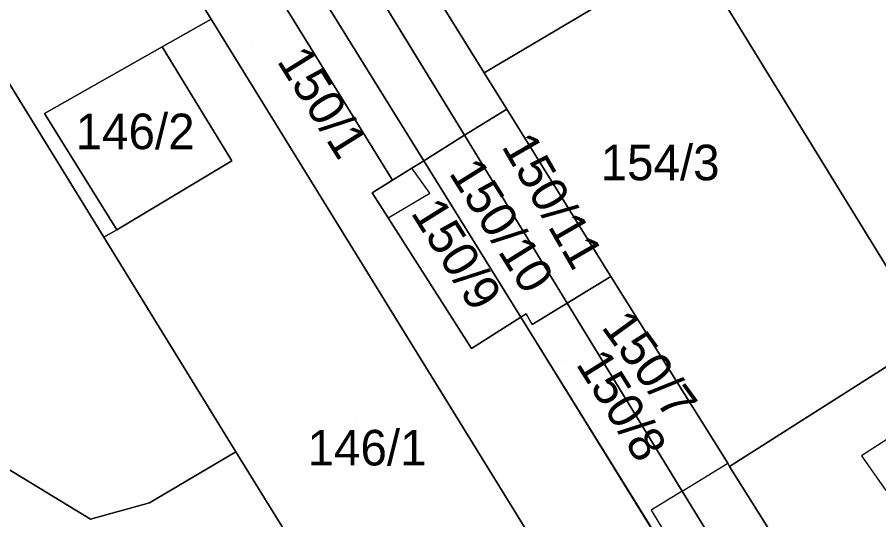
# Model space of a CAD drawing. Extents: x -263943 to -261149, y -1236934 to -1230686.
# Drawn here: x -262544.07 to -262495.61, y -1235802.01 to -1235773.72 of the extents above; entities that cross this region are included whole.
import ezdxf

# ---------------------------------------------------------------- set-up
doc = ezdxf.new("R2010")
doc.units = 0
for name, color, linetype in [('body_kn', 7, 'Continuous'), ('kladpar_druhypozemkov', 7, 'Continuous'), ('kladpar_hranice', 7, 'Continuous'), ('kladpar_parcelnecisla', 7, 'Continuous'), ('kladpar_plochy', 7, 'Continuous'), ('zappar_hrandruhpozemk', 7, 'Continuous')]:
    doc.layers.add(name, color=color, linetype=linetype)

msp = doc.modelspace()

# ---------------------------------------------------------------- linework, layer by layer
at = {"layer": 'body_kn'}
for p, q in [((-262533.17, -1235773.83), (-262533.17, -1235773.83)), ((-262535.91, -1235775.39), (-262535.91, -1235775.39)), ((-262517.8, -1235776.85), (-262517.8, -1235776.85)), ((-262517.8, -1235776.85), (-262517.8, -1235776.85)), ((-262516.53, -1235778.89), (-262516.53, -1235778.89)), ((-262516.53, -1235778.89), (-262516.53, -1235778.89)), ((-262542.53, -1235779.15), (-262542.53, -1235779.15)), ((-262542.53, -1235779.15), (-262542.53, -1235779.15)), ((-262518.91, -1235780.37), (-262518.91, -1235780.37)), ((-262518.91, -1235780.37), (-262518.91, -1235780.37)), ((-262532, -1235781.81), (-262532, -1235781.81)), ((-262521.2, -1235781.8), (-262521.2, -1235781.8)), ((-262521.2, -1235781.8), (-262521.2, -1235781.8)), ((-262521.87, -1235782.22), (-262521.87, -1235782.22)), ((-262521.87, -1235782.22), (-262521.87, -1235782.22)), ((-262522.96, -1235782.9), (-262522.96, -1235782.9)), ((-262522.96, -1235782.9), (-262522.96, -1235782.9)), ((-262524.1, -1235783.61), (-262524.1, -1235783.61)), ((-262520.87, -1235783.62), (-262520.87, -1235783.62)), ((-262523.21, -1235785.01), (-262523.21, -1235785.01)), ((-262523.21, -1235785.01), (-262523.21, -1235785.01)), ((-262538.47, -1235785.69), (-262538.47, -1235785.69)), ((-262539.2, -1235786.1), (-262539.2, -1235786.1)), ((-262510.68, -1235788.32), (-262510.68, -1235788.32)), ((-262510.68, -1235788.32), (-262510.68, -1235788.32)), ((-262513.14, -1235789.82), (-262513.14, -1235789.82)), ((-262515.75, -1235790.61), (-262515.75, -1235790.61)), ((-262515.45, -1235790.42), (-262515.45, -1235790.42)), ((-262515.11, -1235791.02), (-262515.11, -1235791.02)), ((-262518.51, -1235792.36), (-262518.51, -1235792.36)), ((-262531.78, -1235798.18), (-262531.78, -1235798.18)), ((-262531.78, -1235798.18), (-262531.78, -1235798.18)), ((-262496.58, -1235798.41), (-262496.58, -1235798.41)), ((-262504.11, -1235798.82), (-262504.11, -1235798.82)), ((-262504, -1235799), (-262504, -1235799)), ((-262506.67, -1235800.4), (-262506.67, -1235800.4)), ((-262506.67, -1235800.4), (-262506.67, -1235800.4)), ((-262536.63, -1235801.05), (-262536.63, -1235801.05)), ((-262508.42, -1235801.47), (-262508.42, -1235801.47)), ((-262539.95, -1235801.97), (-262539.95, -1235801.97))]:
    msp.add_line(p, q, dxfattribs=at)
at = {"layer": 'kladpar_druhypozemkov'}
for p, q in [((-262530.84, -1235775.34), (-262530.84, -1235775.34)), ((-262537.47, -1235778.5), (-262537.47, -1235778.5)), ((-262517.27, -1235780.12), (-262517.27, -1235780.12)), ((-262507.67, -1235780.9), (-262507.67, -1235780.9)), ((-262519.28, -1235781.91), (-262519.28, -1235781.91)), ((-262517.83, -1235788.26), (-262517.83, -1235788.26)), ((-262511.4, -1235790.94), (-262511.4, -1235790.94)), ((-262513.42, -1235793.1), (-262513.42, -1235793.1)), ((-262525.07, -1235796.5), (-262525.07, -1235796.5))]:
    msp.add_line(p, q, dxfattribs=at)
at = {"layer": 'kladpar_hranice'}
for p, q in [((-262521.2, -1235781.8), (-262543.94, -1235745.11)), ((-262543.94, -1235745.11), (-262521.2, -1235781.8)), ((-262518.91, -1235780.37), (-262537.03, -1235750.74)), ((-262537.03, -1235750.74), (-262518.91, -1235780.37)), ((-262518.91, -1235780.37), (-262516.53, -1235778.89)), ((-262518.91, -1235780.37), (-262521.2, -1235781.8)), ((-262521.2, -1235781.8), (-262518.91, -1235780.37)), ((-262518.91, -1235780.37), (-262513.14, -1235789.82)), ((-262513.14, -1235789.82), (-262518.91, -1235780.37)), ((-262521.87, -1235782.22), (-262521.2, -1235781.8)), ((-262521.2, -1235781.8), (-262515.75, -1235790.61)), ((-262515.75, -1235790.61), (-262521.2, -1235781.8)), ((-262513.14, -1235789.82), (-262510.68, -1235788.32)), ((-262515.75, -1235790.61), (-262504.71, -1235808.42)), ((-262504.71, -1235808.42), (-262515.75, -1235790.61))]:
    msp.add_line(p, q, dxfattribs=at)
for points in [[(-262541.39, -1235743.6), (-262539.16, -1235742.28), (-262528.72, -1235759.26), (-262517.8, -1235776.85)], [(-262522.96, -1235782.9), (-262545.68, -1235746.14), (-262543.94, -1235745.11)], [(-262509.8, -1235811.73), (-262533.17, -1235773.83), (-262535.2, -1235770.52), (-262548.92, -1235748.31), (-262549, -1235748.17), (-262545.68, -1235746.14), (-262522.96, -1235782.9), (-262524.1, -1235783.61), (-262523.21, -1235785.01), (-262518.51, -1235792.36), (-262515.75, -1235790.61)], [(-262542.53, -1235779.15), (-262538.47, -1235785.69), (-262539.2, -1235786.1), (-262544.99, -1235776.68), (-262548.44, -1235771.06), (-262550.62, -1235767.5), (-262557.92, -1235755.61), (-262559.32, -1235753.33), (-262549.6, -1235747.32), (-262549, -1235748.17), (-262548.92, -1235748.31), (-262535.2, -1235770.52), (-262533.17, -1235773.83), (-262535.91, -1235775.39), (-262542.53, -1235779.15)], [(-262528.72, -1235759.26), (-262520.33, -1235754.87), (-262519.51, -1235756.18), (-262516.32, -1235754.26), (-262517.03, -1235753.13), (-262516.64, -1235752.93), (-262514.54, -1235756.27), (-262509.27, -1235764.66), (-262506.14, -1235769.93), (-262517.8, -1235776.85), (-262528.72, -1235759.26)], [(-262531.78, -1235798.18), (-262536.63, -1235801.05), (-262539.95, -1235801.97), (-262549.37, -1235796.26), (-262555.31, -1235791.15), (-262561.99, -1235780.36), (-262572.32, -1235764.21), (-262573.59, -1235762.17), (-262570.55, -1235760.29), (-262569.21, -1235762.34), (-262571.73, -1235763.96), (-262570.81, -1235765.31), (-262567.49, -1235770.17), (-262565.09, -1235768.67), (-262564.94, -1235768.9), (-262554.5, -1235775.12), (-262548.44, -1235771.06), (-262544.99, -1235776.68), (-262539.2, -1235786.1), (-262531.78, -1235798.18)], [(-262576.07, -1235768.53), (-262575.73, -1235766.24), (-262572.32, -1235764.21), (-262561.99, -1235780.36), (-262555.31, -1235791.15), (-262549.37, -1235796.26), (-262539.95, -1235801.97), (-262536.63, -1235801.05), (-262531.78, -1235798.18), (-262515.86, -1235823.92), (-262489.14, -1235866.73)], [(-262467.61, -1235831.73), (-262477.05, -1235816.42), (-262492.69, -1235791.8), (-262504.11, -1235773.23), (-262490.4, -1235765.13), (-262475.84, -1235788.48), (-262462.67, -1235809.8), (-262437.59, -1235849.88), (-262453.44, -1235854.31), (-262467.61, -1235831.73)], [(-262510.68, -1235788.32), (-262516.53, -1235778.89), (-262517.8, -1235776.85), (-262506.14, -1235769.93), (-262504.11, -1235773.23), (-262492.69, -1235791.8), (-262504, -1235799), (-262504.11, -1235798.82), (-262510.68, -1235788.32)], [(-262531.78, -1235798.18), (-262539.2, -1235786.1), (-262538.47, -1235785.69), (-262532, -1235781.81), (-262535.91, -1235775.39), (-262533.17, -1235773.83), (-262509.8, -1235811.73), (-262506.58, -1235817.08), (-262515.86, -1235823.92), (-262531.78, -1235798.18)], [(-262542.53, -1235779.15), (-262535.91, -1235775.39), (-262532, -1235781.81), (-262538.47, -1235785.69), (-262542.53, -1235779.15)], [(-262517.8, -1235776.85), (-262516.53, -1235778.89), (-262518.91, -1235780.37)], [(-262516.53, -1235778.89), (-262510.68, -1235788.32), (-262513.14, -1235789.82)], [(-262521.2, -1235781.8), (-262521.87, -1235782.22), (-262522.96, -1235782.9)], [(-262515.75, -1235790.61), (-262518.51, -1235792.36), (-262523.21, -1235785.01), (-262524.1, -1235783.61), (-262522.96, -1235782.9), (-262521.87, -1235782.22)], [(-262510.68, -1235788.32), (-262504.11, -1235798.82), (-262504, -1235799), (-262500.01, -1235805.37), (-262501.89, -1235806.59), (-262502.6, -1235807.05)], [(-262515.75, -1235790.61), (-262515.45, -1235790.42), (-262515.11, -1235791.02), (-262513.14, -1235789.82)], [(-262513.14, -1235789.82), (-262515.11, -1235791.02), (-262515.45, -1235790.42), (-262515.75, -1235790.61)], [(-262502.6, -1235807.05), (-262504.24, -1235804.37), (-262506.67, -1235800.4), (-262513.14, -1235789.82)], [(-262513.14, -1235789.82), (-262506.67, -1235800.4), (-262504.24, -1235804.37), (-262502.6, -1235807.05)], [(-262458.14, -1235862.12), (-262467.75, -1235846.97), (-262471.24, -1235841.22), (-262475.72, -1235844.19), (-262500.01, -1235805.37), (-262504, -1235799), (-262492.69, -1235791.8), (-262477.05, -1235816.42), (-262467.61, -1235831.73), (-262453.44, -1235854.31), (-262450.19, -1235859.48)]]:
    msp.add_lwpolyline(points, dxfattribs=at)
at = {"layer": 'kladpar_plochy'}
for p, q in [((-262504, -1235799), (-262492.69, -1235791.8)), ((-262500.01, -1235805.37), (-262504, -1235799))]:
    msp.add_line(p, q, dxfattribs=at)
for points in [[(-262517.8, -1235776.85), (-262516.53, -1235778.89), (-262518.91, -1235780.37), (-262537.03, -1235750.74), (-262535.15, -1235749.65), (-262537.86, -1235744.98), (-262539.87, -1235746.09), (-262541.39, -1235743.6), (-262539.16, -1235742.28), (-262528.72, -1235759.26)], [(-262518.91, -1235780.37), (-262521.2, -1235781.8), (-262543.94, -1235745.11), (-262541.39, -1235743.6), (-262539.87, -1235746.09), (-262541.52, -1235747.01), (-262538.64, -1235751.68), (-262537.03, -1235750.74)], [(-262522.96, -1235782.9), (-262545.68, -1235746.14), (-262543.94, -1235745.11), (-262521.2, -1235781.8), (-262521.87, -1235782.22)], [(-262509.8, -1235811.73), (-262533.17, -1235773.83), (-262535.2, -1235770.52), (-262548.92, -1235748.31), (-262549, -1235748.17), (-262545.68, -1235746.14), (-262522.96, -1235782.9), (-262524.1, -1235783.61), (-262523.21, -1235785.01), (-262518.51, -1235792.36), (-262515.75, -1235790.61), (-262504.71, -1235808.42)], [(-262542.53, -1235779.15), (-262538.47, -1235785.69), (-262539.2, -1235786.1), (-262544.99, -1235776.68), (-262548.44, -1235771.06), (-262550.62, -1235767.5), (-262557.92, -1235755.61), (-262559.32, -1235753.33), (-262549.6, -1235747.32), (-262549, -1235748.17), (-262548.92, -1235748.31), (-262535.2, -1235770.52), (-262533.17, -1235773.83), (-262535.91, -1235775.39)], [(-262528.72, -1235759.26), (-262520.33, -1235754.87), (-262519.51, -1235756.18), (-262516.32, -1235754.26), (-262517.03, -1235753.13), (-262516.64, -1235752.93), (-262514.54, -1235756.27), (-262509.27, -1235764.66), (-262506.14, -1235769.93), (-262517.8, -1235776.85)], [(-262531.78, -1235798.18), (-262536.63, -1235801.05), (-262539.95, -1235801.97), (-262549.37, -1235796.26), (-262555.31, -1235791.15), (-262561.99, -1235780.36), (-262572.32, -1235764.21), (-262573.59, -1235762.17), (-262570.55, -1235760.29), (-262569.21, -1235762.34), (-262571.73, -1235763.96), (-262570.81, -1235765.31), (-262567.49, -1235770.17), (-262565.09, -1235768.67), (-262564.94, -1235768.9), (-262554.5, -1235775.12), (-262548.44, -1235771.06), (-262544.99, -1235776.68), (-262539.2, -1235786.1)], [(-262467.61, -1235831.73), (-262477.05, -1235816.42), (-262492.69, -1235791.8), (-262504.11, -1235773.23), (-262490.4, -1235765.13), (-262475.84, -1235788.48), (-262462.67, -1235809.8), (-262437.59, -1235849.88), (-262453.44, -1235854.31)], [(-262510.68, -1235788.32), (-262516.53, -1235778.89), (-262517.8, -1235776.85), (-262506.14, -1235769.93), (-262504.11, -1235773.23), (-262492.69, -1235791.8), (-262504, -1235799), (-262504.11, -1235798.82)], [(-262531.78, -1235798.18), (-262539.2, -1235786.1), (-262538.47, -1235785.69), (-262532, -1235781.81), (-262535.91, -1235775.39), (-262533.17, -1235773.83), (-262509.8, -1235811.73), (-262506.58, -1235817.08), (-262515.86, -1235823.92)], [(-262542.53, -1235779.15), (-262535.91, -1235775.39), (-262532, -1235781.81), (-262538.47, -1235785.69)], [(-262516.53, -1235778.89), (-262510.68, -1235788.32), (-262513.14, -1235789.82), (-262518.91, -1235780.37)], [(-262521.2, -1235781.8), (-262518.91, -1235780.37), (-262513.14, -1235789.82), (-262515.11, -1235791.02), (-262515.45, -1235790.42), (-262515.75, -1235790.61)], [(-262521.87, -1235782.22), (-262521.2, -1235781.8), (-262515.75, -1235790.61), (-262518.51, -1235792.36), (-262523.21, -1235785.01), (-262524.1, -1235783.61), (-262522.96, -1235782.9)], [(-262510.68, -1235788.32), (-262504.11, -1235798.82), (-262504, -1235799), (-262500.01, -1235805.37), (-262501.89, -1235806.59), (-262502.6, -1235807.05), (-262504.24, -1235804.37), (-262506.67, -1235800.4), (-262513.14, -1235789.82)], [(-262502.6, -1235807.05), (-262504.71, -1235808.42), (-262515.75, -1235790.61), (-262515.45, -1235790.42), (-262515.11, -1235791.02), (-262513.14, -1235789.82), (-262506.67, -1235800.4), (-262504.24, -1235804.37)]]:
    msp.add_lwpolyline(points, close=True, dxfattribs=at)
msp.add_lwpolyline([(-262605.67, -1235871.49), (-262620.33, -1235848.64), (-262635.19, -1235825.26), (-262636.43, -1235823.31), (-262646.33, -1235807.76), (-262611.04, -1235787.25), (-262583.9, -1235771.05), (-262582.11, -1235772.41), (-262576.07, -1235768.53), (-262575.73, -1235766.24), (-262572.32, -1235764.21), (-262561.99, -1235780.36), (-262555.31, -1235791.15), (-262549.37, -1235796.26), (-262539.95, -1235801.97), (-262536.63, -1235801.05), (-262531.78, -1235798.18), (-262515.86, -1235823.92), (-262489.14, -1235866.73)], dxfattribs=at)
at = {"layer": 'zappar_hrandruhpozemk'}
for p, q in [((-262520.87, -1235783.62), (-262521.87, -1235782.22)), ((-262523.21, -1235785.01), (-262520.87, -1235783.62)), ((-262506.67, -1235800.4), (-262504.11, -1235798.82)), ((-262506.67, -1235800.4), (-262508.42, -1235801.47)), ((-262508.42, -1235801.47), (-262505.11, -1235806.82))]:
    msp.add_line(p, q, dxfattribs=at)
msp.add_lwpolyline([(-262491.08, -1235794.85), (-262496.58, -1235798.41), (-262495.22, -1235800.36)], dxfattribs=at)

# ---------------------------------------------------------------- texts
at = {"layer": 'kladpar_parcelnecisla'}
for s, rotation, p in [('150/1', 302, (-262529.5, -1235776.186)), ('150/11', 300, (-262516.86, -1235780.989)), ('150/10', 302, (-262519.827, -1235782.491)), ('150/9', 302, (-262521.967, -1235784.728)), ('150/7', 306, (-262511.256, -1235791.17)), ('150/8', 302, (-262512.68, -1235793.238))]:
    msp.add_text(s, height=2, rotation=rotation, dxfattribs=at).set_placement(p)
for s, p in [('146/2', (-262540.786, -1235781.15)), ('154/3', (-262511.257, -1235782.9)), ('146/1', (-262527.74, -1235798.95))]:
    msp.add_text(s, height=2, dxfattribs=at).set_placement(p)

doc.saveas('drawing.dxf')
